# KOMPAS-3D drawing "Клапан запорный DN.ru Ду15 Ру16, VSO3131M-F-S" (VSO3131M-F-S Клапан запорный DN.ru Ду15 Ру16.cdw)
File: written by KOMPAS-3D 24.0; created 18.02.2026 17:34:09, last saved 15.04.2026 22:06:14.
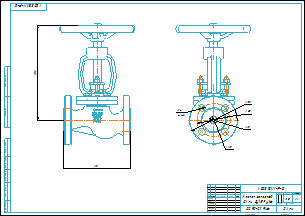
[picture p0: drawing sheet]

Document properties: Автор: R2D2; Форматы листов документа: A2; Полное имя файла: исходные материалы\VSO3131M-F-S Клапан запорный DN.ru Ду15 Ру16.m3d; Масса: 3.45; Наименование: Клапан запорный DN.ru Ду15 Ру16; Количество листов документа: 1; Примечание: D090-02946

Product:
- Part/product: Клапан запорный DN.ru Ду15 Ру16  | designation VSO3131M-F-S
    Масса: 3.45
    Раздел спецификации: Прочие изделия
    Примечание: D090-02946

Views: Вид 1, Спереди, Проекционный вид 2
Referenced files in E:\Работа\Зайцев\VSO1121M-F-S Клапан запорный сальниковый DN.ru\DN15\: VSO1121M-F-S Клапан запорный DN.ru Ду15 Ру16.m3d
Referenced files in E:\Работа\Зайцев\VSO3131M-F-S Клапан запорный DN.ru Ду15-100 Ру16\DN15\исходные материалы\: VSO3131M-F-S Клапан запорный DN.ru Ду15 Ру16.m3d
Referenced files in E:\Работа\Зайцев\Для компаса\: чертеж DN.ru А3.cdt
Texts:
  VSO3131M-F-S
  чертеж DN.ru А3.cdt
  Клапан запорный
  DN.ru Ду15 Ру16
  Клапан запорный DN.ru Ду15 Ру16
  VSO3131M-F-S Клапан запорный DN.ru Ду15 Ру16
Dimensions and other numbers on the sheet: 0; 3; 2; 4; 130; 185; 95; 65; 15; 14; 4 отв.; 1:1; 1; 3,45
